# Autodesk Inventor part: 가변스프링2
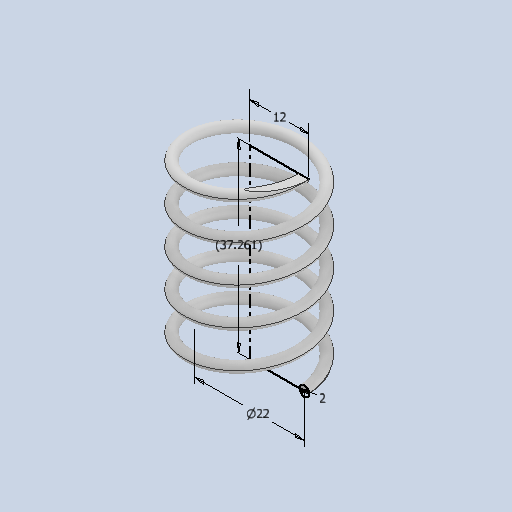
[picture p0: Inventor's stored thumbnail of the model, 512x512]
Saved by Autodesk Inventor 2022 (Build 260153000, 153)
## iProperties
Created: 2021-07
Part Number: 가변스프링2
Material: 일반
Document SubType Name: Modeling
Designer: micke
Density: 1 g/cm^3
Appearance: 기본값
Author: micke
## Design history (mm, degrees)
sketch "스케치1"
  geometry: L1 (0, 0)-(0, 37.261); L2 (0, 37.261)-(12, 37.261); L3 (0, 0)-(11, 0); C1 r 1 at (11, 0)
  constraints: 6 end point, 2 horizontal, 1 centre point, 1 coincident, 1 vertical
  dimensions: "d0" = 37.2612 distance of L1.start L1.end (derived); "d1" = 2 diameter of C1; "d2" = 22 diameter of L3.end L1; "d3" = 12 distance of L1.end L2.end
feature "코일1" sketch "스케치1" pitch "d4" = 10; turns "d6" = 5; dims "d5" = 37.2612 (= d0), "d7" = 0, angle "d8" = 90 deg, angle "d9" = 90 deg, "d10" = 0, "d11" = 0
sketch "스케치2"
  geometry: L1 (37.261, 12.5)-(0, 12.5); L2 (0, 12.5)-(0, -12.5); L3 (0, -12.5)-(37.261, -12.5); L4 (37.261, -12.5)-(37.261, 12.5); 2 further points
  constraints: 8 end point, 2 parallel, 1 coincident, 1 horizontal, 1 midpoint, 1 perpendicular
  dimensions: "d12" = 37.2612 distance of L1.start L1.end (= d0); "d13" = 25 distance of L3.end L1.start
extrude "돌출1" sketch "스케치2" extent not by distance; stored distance "d14" = 0; taper "d15" = 0 deg
node "솔리드1"
feature "A9D066F2-1C7D-4E18-AEED-F7BC21143FA4" dims "d4" = 10, "d5" = 37.2612 (= d0), "d6" = 50, "d7" = 0, "d8" = 90 deg, "d9" = 90 deg, "d10" = 0, "d11" = 0
